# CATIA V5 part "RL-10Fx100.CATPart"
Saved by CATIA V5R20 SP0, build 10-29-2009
Part number: _RL-10Fx100
Definition: NONE
Nomenclature: _RL-10Fx100
Source: Unknown
Description: PART-_RL-10Fx100-DESC
Bounding box of the stored display mesh (mm): x -100 to 12.5, y -5.8 to 5.8, z -5.8 to 5.8
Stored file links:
  C:\Users\Utente\Desktop\IO LAVORO\3D X SITO CF\X SITO\PLASTICA\RLF\RL-10Fx100.CATPart
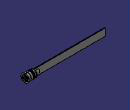
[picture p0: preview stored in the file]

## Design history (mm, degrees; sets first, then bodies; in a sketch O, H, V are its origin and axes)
Body1 "_RL-10Fx100" (main body)
  Solid1: solid without history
